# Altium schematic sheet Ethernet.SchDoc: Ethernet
size A4; DocumentNumber: MB1167; Revision: B.1; SheetNumber: 7; SheetTotal: 17; Project: STM327x6G-EVAL
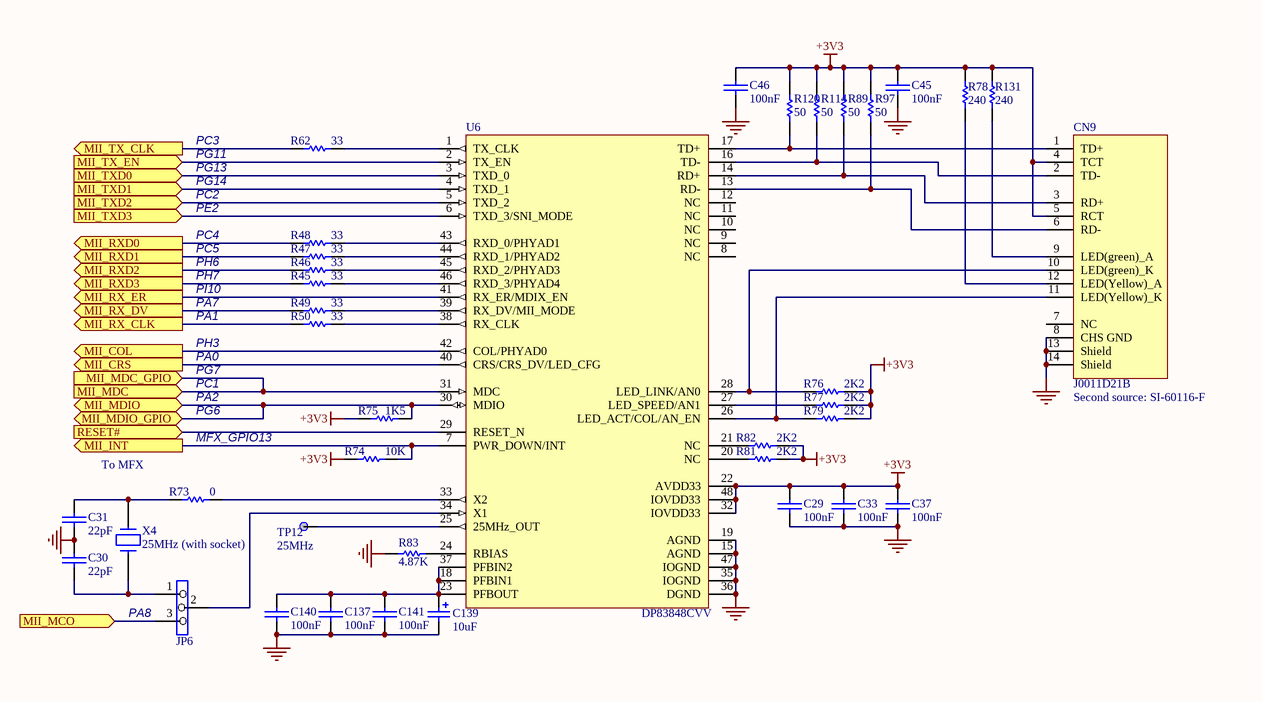
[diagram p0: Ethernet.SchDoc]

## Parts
C29  100nF  [0603C]
C30  22pF  [0603C]
C31  22pF  [0603C]
C33  100nF  [0603C]
C37  100nF  [0603C]
C45  100nF  [0603C]
C46  100nF  [0603C]
C137  100nF  [0603C]
C139  10uF  [TAN-A]
C140  100nF  [0603C]
C141  100nF  [0603C]
CN9  J0011D21B  [RJ45_J0011D01BNL]
JP6  (no value)  [SIP3]
R45  33  [0603R]
R46  33  [0603R]
R47  33  [0603R]
R48  33  [0603R]
R49  33  [0603R]
R50  33  [0603R]
R62  33  [0603R]
R73  0  [0603R]
R74  10K  [0603R]
R75  1K5  [0603R]
R76  2K2  [0603R]
R77  2K2  [0603R]
R78  240  [0603R]
R79  2K2  [0603R]
R81  2K2  [0603R]
R82  2K2  [0603R]
R83  4.87K  [0603R]
R89  50  [0603R]
R97  50  [0603R]
R114  50  [0603R]
R120  50  [0603R]
R131  240  [0603R]
TP12  25MHz  [TP]
U6  DP83848CVV  [LQFP48_0R5_9X9]
X4  25MHz (with socket)  [XTAL_socket]

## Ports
MII_COL (out), MII_CRS (out), MII_INT (out), MII_MCO (in), MII_MDC (in), MII_MDC_GPIO (in), MII_MDIO (bidir), MII_MDIO_GPIO (bidir), MII_RX_CLK (out), MII_RX_DV (out), MII_RX_ER (out), MII_RXD0 (out), MII_RXD1 (out), MII_RXD2 (out), MII_RXD3 (out), MII_TX_CLK (out), MII_TX_EN (in), MII_TXD0 (in), MII_TXD1 (in), MII_TXD2 (in), MII_TXD3 (in), RESET# (in)

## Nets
+3V3: C29.1 C33.2 C37.2 C45.2 C46.2 CN9.4(TCT) CN9.5(RCT) R74.1 R75.2 R76.2 R77.2 R78.2 R79.2 R81.2 R82.2 R89.1 R97.1 R114.1 R120.1 R131.2 U6.22(AVDD33) U6.32(IOVDD33) U6.48(IOVDD33)
GND: C29.2 C30.2 C31.1 C33.1 C37.1 C45.1 C46.1 C137.1 C139.2 C140.2 C141.1 CN9.8(CHS_GND) CN9.13(Shield) CN9.14(Shield) R83.1 U6.15(AGND) U6.19(AGND) U6.35(IOGND) U6.36(DGND) U6.47(IOGND)
MII_COL: U6.42(COL/PHYAD0) ; port MII_COL
MII_CRS: U6.40(CRS/CRS_DV/LED_CFG) ; port MII_CRS
MII_INT: R74.2 U6.7(PWR_DOWN/INT) ; port MII_INT
MII_MCO: JP6.3 ; port MII_MCO
MII_MDC: U6.31(MDC) ; port MII_MDC, port MII_MDC_GPIO
MII_MDIO: R75.1 U6.30(MDIO) ; port MII_MDIO, port MII_MDIO_GPIO
MII_RX_CLK: R50.2 ; port MII_RX_CLK
MII_RX_DV: R49.2 ; port MII_RX_DV
MII_RX_ER: U6.41(RX_ER/MDIX_EN) ; port MII_RX_ER
MII_RXD0: R48.2 ; port MII_RXD0
MII_RXD1: R47.2 ; port MII_RXD1
MII_RXD2: R46.2 ; port MII_RXD2
MII_RXD3: R45.2 ; port MII_RXD3
MII_TX_CLK: R62.2 ; port MII_TX_CLK
MII_TX_EN: U6.2(TX_EN) ; port MII_TX_EN
MII_TXD0: U6.3(TXD_0) ; port MII_TXD0
MII_TXD1: U6.4(TXD_1) ; port MII_TXD1
MII_TXD2: U6.5(TXD_2) ; port MII_TXD2
MII_TXD3: U6.6(TXD_3/SNI_MODE) ; port MII_TXD3
RESET#: U6.29(RESET_N) ; port RESET#
NetC30_1: C30.1 JP6.1 X4.1
NetC31_2: C31.2 R73.2 X4.2
NetC137_2: C137.2 C139.1 C140.1 C141.2 U6.18(PFBIN1) U6.23(PFBOUT) U6.37(PFBIN2)
NetCN9_1: CN9.1(TD+) R120.2 U6.17(TD+)
NetCN9_2: CN9.2(TD-) R114.2 U6.16(TD-)
NetCN9_3: CN9.3(RD+) R89.2 U6.14(RD+)
NetCN9_6: CN9.6(RD-) R97.2 U6.13(RD-)
NetCN9_9: CN9.9(LED(green)_A) R131.1
NetCN9_10: CN9.10(LED(green)_K) R76.1 U6.28(LED_LINK/AN0)
NetCN9_11: CN9.11(LED(Yellow)_K) R79.1 U6.26(LED_ACT/COL/AN_EN)
NetCN9_12: CN9.12(LED(Yellow)_A) R78.1
NetJP6_2: JP6.2 U6.34(X1)
NetR45_1: R45.1 U6.46(RXD_3/PHYAD4)
NetR46_1: R46.1 U6.45(RXD_2/PHYAD3)
NetR47_1: R47.1 U6.44(RXD_1/PHYAD2)
NetR48_1: R48.1 U6.43(RXD_0/PHYAD1)
NetR49_1: R49.1 U6.39(RX_DV/MII_MODE)
NetR50_1: R50.1 U6.38(RX_CLK)
NetR62_1: R62.1 U6.1(TX_CLK)
NetR73_1: R73.1 U6.33(X2)
NetR77_1: R77.1 U6.27(LED_SPEED/AN1)
NetR81_1: R81.1 U6.20(NC)
NetR82_1: R82.1 U6.21(NC)
NetR83_2: R83.2 U6.24(RBIAS)
NetTP12_1: TP12.1 U6.25(25MHz_OUT)

Not connected (* = marked no-connect by the designer): CN9 7(NC); U6 8(NC) 9(NC) 10(NC) 11(NC) 12(NC)

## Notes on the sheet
- PC3
- PG11
- PG13
- PG14
- PC2
- PE2
- PC4
- PC5
- PH6
- PH7
- PI10
- PA7
- PH3
- PA1
- PA0
- PC1
- PA2
- PG7
- PG6
- (near CN9) Second source: SI-60116-F
- To MFX
- MFX_GPIO13
- (near JP6) PA8

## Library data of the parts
C29-C31 C33 C37 C45 C46 C137 C140 C141 = CAP: Capacitor
C139 = Cap Pol1: Polarized Capacitor (Radial)
JP6 = Jumper3
R45-R50 R62 R73-R79 R81-R83 R89 R97 R114 R120 R131 = Res1: Resistor; Value: 1K
TP12 = TP
X4 = CRYSTAL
